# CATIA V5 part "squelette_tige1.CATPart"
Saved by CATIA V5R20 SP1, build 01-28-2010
Part number: squelette_tige1
Publications: "Droite.1", "Droite.2", "Plan.2"
Bounding box of the stored display mesh (mm): x 0 to 0, y 100.242 to 9059679, z -4233647.5 to 89.862
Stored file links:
  C:\Users\Fox\Desktop\IAO Projet\A RENDRE\Sauvegarde IFMA\squelette_tige1.CATPart
  C:\Users\Fox\Desktop\IAO Projet\A RENDRE\Sauvegarde IFMA\squelette.CATProduct
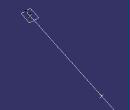
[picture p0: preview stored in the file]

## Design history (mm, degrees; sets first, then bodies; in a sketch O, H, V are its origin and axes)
Set1
  Line1: type PtDir, RefPoint Point1, Direction Line3, Start 0, End 10
  Line2: type Angle, RefPoint Point1, Curve Line1, Support Plane2, Start -10, End 10, Angle 90
  Plane1: type Normal, Curve Line2, RefPoint Point1
Set2
  Point1: linked copy from another document
  Point2: linked copy from another document
  Plane2: linked copy from another document
  Line3: linked copy from another document
Body1 (main body)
